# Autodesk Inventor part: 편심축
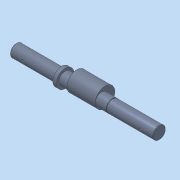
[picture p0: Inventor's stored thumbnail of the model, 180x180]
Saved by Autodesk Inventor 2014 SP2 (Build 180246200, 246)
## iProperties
Manager: 한국ATC센터
Company: 한국ATC센터
Created: 2014-10
Part Number: 편심축
Document SubType Name: Modeling
Designer: 한국ATC센터
Density: 7.86 g/cm^3
Material: 강, 연강
Mass: 1420.77 g
Surface Area: 286.546 cm^2
Volume: 180.759 cm^3
Appearance: 강철
Author: KYOUNG IL JANG
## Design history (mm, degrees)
sketch "스케치1"
  geometry: L1 (-142, 0)-(142, 0); L2 (-142, 0)-(-142, 12.5); L3 (-142, 12.5)-(-52, 12.5); L4 (-52, 12.5)-(-52, 17.5); L5 (-52, 17.5)-(-45, 17.5); L6 (-45, 17.5)-(-45, 12.5); L7 (-45, 12.5)-(48.65, 12.5); L8 (48.65, 12.5)-(48.65, 11.95); L9 (48.65, 11.95)-(50, 11.95); L10 (50, 11.95)-(50, 12.5); L11 (50, 12.5)-(142, 12.5); L12 (142, 12.5)-(142, 0); L13 (109, 12.5)-(109, 9.1); L14 (109, 9.1)-(134, 9.1); L15 (134, 9.1)-(134, 12.5); L16 (117, -12.5)-(119.5, -12.5); L17 (119.5, -12.5)-(117, -10); L18 (117, -10)-(117, -12.5); L19 (-109, 12.5)-(-109, 9.1); L20 (-109, 9.1)-(-134, 9.1); L21 (-134, 9.1)-(-134, 12.5); L22 (-117, -12.5)-(-117, -10); L23 (-117, -10)-(-114.5, -12.5); L24 (-114.5, -12.5)-(-117, -12.5); 2 further points
  constraints: 48 end point, 11 parallel, 8 perpendicular, 5 collinear, 4 point on line, 1 coincident, 1 horizontal, 1 midpoint, 1 vertical
  dimensions: "d0" = 284 distance of L1.start L1.end (derived); "d1" = 25 diameter of L3 L1; "d2" = 35 diameter of L5 L1; "d3" = 90 distance of L2.end L3.end; "d4" = 187 distance between parallel lines of L12 L6; "d6" = 1.35 distance of L8.end L9.end; "d7" = 23.9 diameter of L9 L1; "d8" = 3.4 distance between parallel lines of L14 L11; "d9" = 8 distance between parallel lines of L15 L12; "d10" = 25 distance of L13.end L14.end; "d11" = 25 diameter of L16 L1 (= d1); "d12" = 25 distance from line of L12 L16.start; "d13" = 45 deg angle of L17 L18; "d14" = 5 diameter of L16.end L18; "d27" = 92 distance between parallel lines of L10 L12; "d32" = 7 distance of L4.end L5.end; "d33" = 8 distance between parallel lines of L2 L21; "d34" = 25 distance between parallel lines of L21 L19; "d35" = 3.4 distance between parallel lines of L3 L20; "d36" = 25 distance from line of L22.start L2; "d37" = 5 diameter of L23.end L22
revolve "회전1" stored, may be unused: angle "d15" = 90 deg
revolve "회전2" stored, may be unused: angle "d16" = 90 deg
revolve "회전3" stored, may be unused: angle "d38" = 90 deg
extrude "돌출1" cut sketch "스케치1" stored distance "d17" = 8; taper "d18" = 0 deg
fillet "모깎기1" dims "d19" = 4
node "작업 평면1"
sketch "스케치2"
  geometry: L1 (12.99, -6.5)-(8.66, -14); L2 (-12.99, -6.5)-(-8.66, -14); C1 r 12.5 at (0, 0) reference; C2 r 19.5 at (0, 7); A1 r 15 centre (0, 1) between (12.99, -6.5) and (-12.99, -6.5); A2 r 10 centre (0, -9) between (-8.66, -14) and (8.66, -14); 1 further point
  constraints: 5 tangent, 4 end point, 4 point on circle, 3 centre point, 3 vertical alignment
  dimensions: "d21" = 7 distance of point (0, 0) C2.centre; "d30" = 39 diameter of C2 (derived); "d39" = 10 distance of A2.centre A1.centre; "d40" = 30 diameter of A1; "d41" = 20 diameter of A2; "d42" = 1 distance of point (0, 0) A1.centre
extrude "돌출2" join sketch "스케치2" distance "d22" = 56; taper "d23" = 0 deg
chamfer "모따기1" distance "d24" = 1; stored, may be unused: second distance "d25" = 2, angle "d26" = 45 deg
node "솔리드1"
other parameters: "d20" = 16
